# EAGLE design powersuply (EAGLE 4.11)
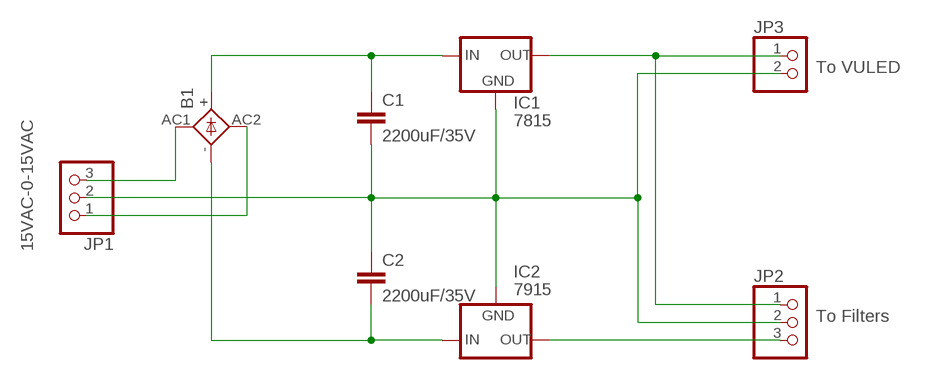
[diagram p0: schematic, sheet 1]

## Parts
B1  1KAB  [1KAB]
C1  2200uF/35V  C7.5/6  [C7.5B6]
C2  2200uF/35V  C7.5/6  [C7.5B6]
IC1  7815  78XXS  [78XXS]
IC2  7915  79XXS  [79XXS]
JP1  PINHD-1X3  [1X03]
JP2  PINHD-1X3  [1X03]
JP3  PINHD-1X2  [1X02]

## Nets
N$1: C1.2 C2.1 IC1.GND IC2.GND JP1.2 JP2.2 JP3.2
N$2: B1.+ C1.1 IC1.IN
N$3: B1.- C2.2 IC2.IN
N$5: B1.AC2 JP1.1
N$6: B1.AC1 JP1.3
N$7: IC2.OUT JP2.3
N$8: IC1.OUT JP2.1 JP3.1

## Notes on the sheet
- To VULED
- 15VAC-0-15VAC
- To Filters

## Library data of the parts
B1 = rectifier:1KAB: RECTIFIER grid 5,08 x 5,08 mm
C1 C2 = capacitor-wima:C: CAPACITOR
IC1 = v-reg:78XXS: VOLTAGE REGULATOR
IC2 = v-reg:79XXS: VOLTAGE REGULATOR
JP1 JP2 = pinhead:PINHD-1X3: PIN HEADER
JP3 = pinhead:PINHD-1X2: PIN HEADER

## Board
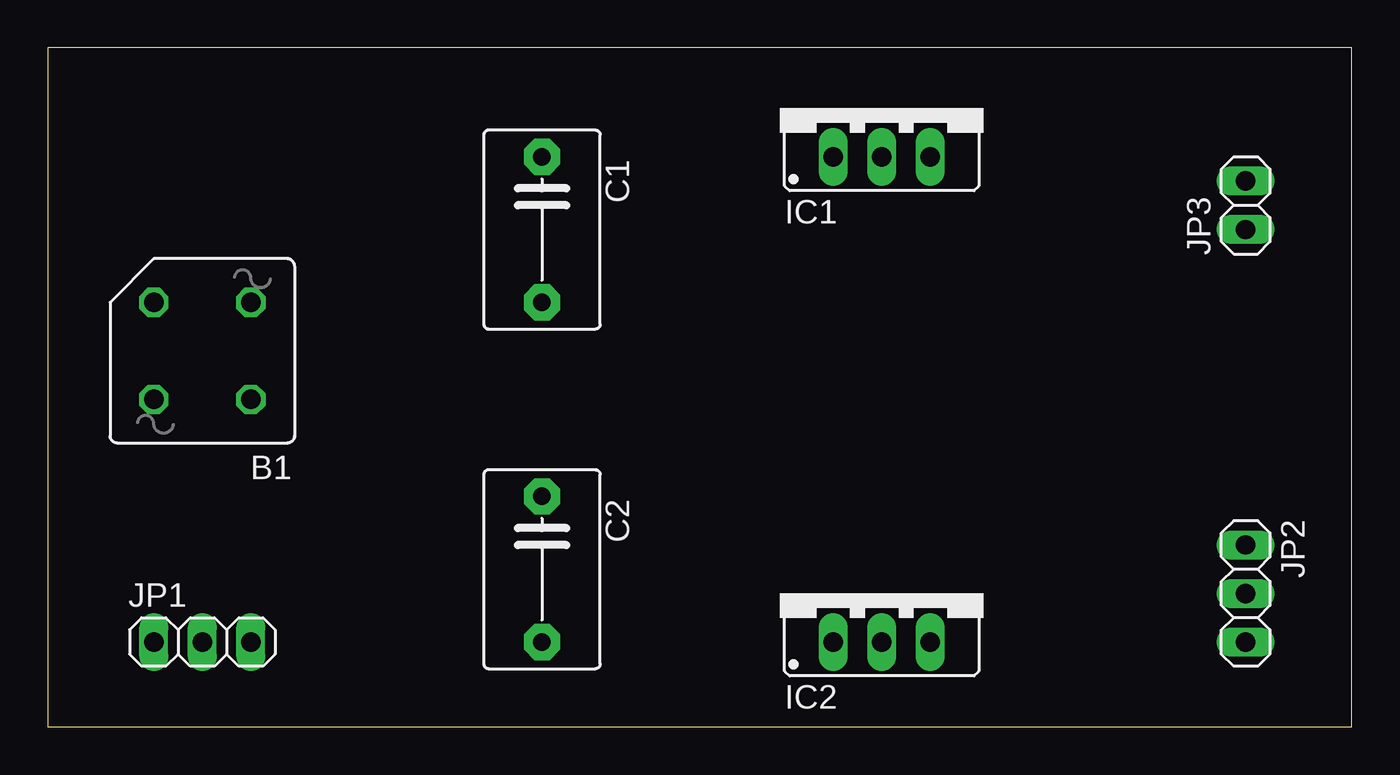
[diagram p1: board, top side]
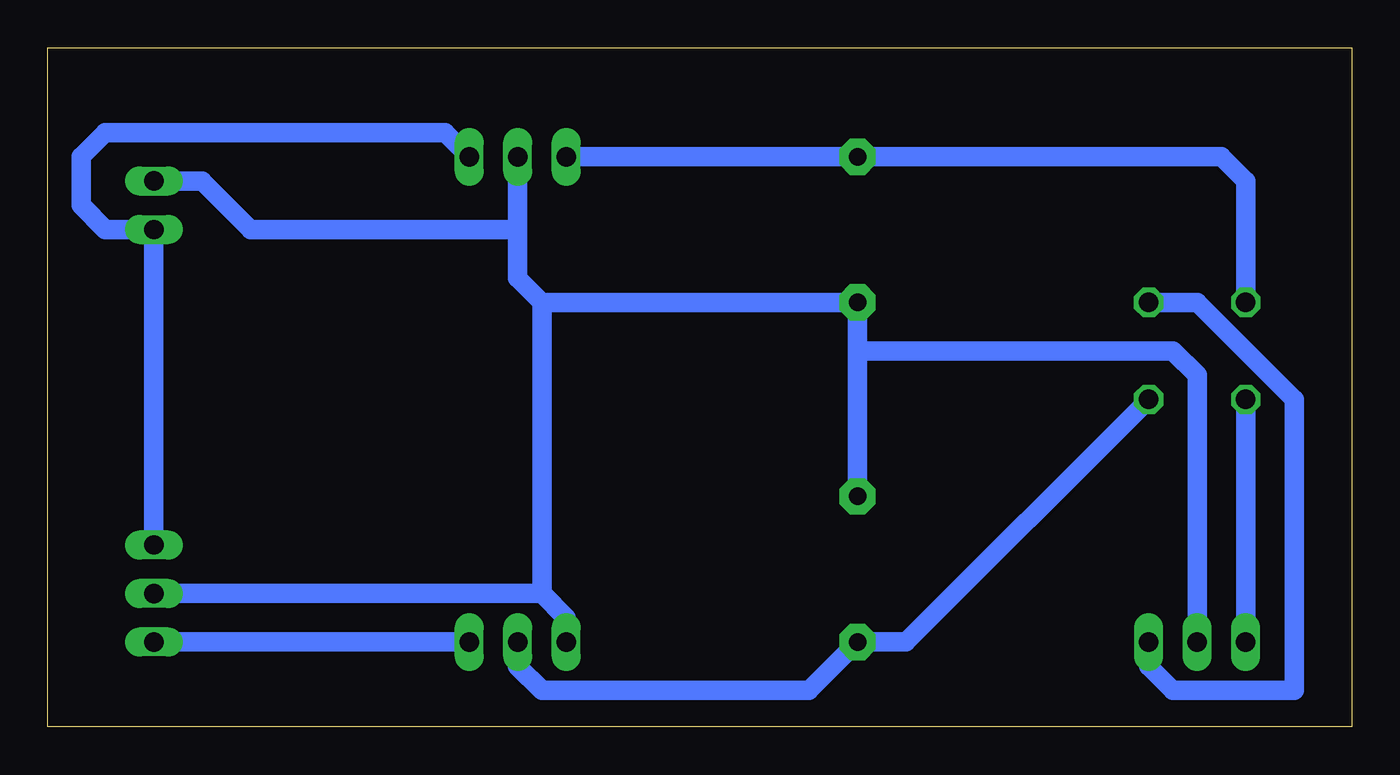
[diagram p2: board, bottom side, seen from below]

Size 68.25 x 35.55 mm. Coordinates in mm from the lower left corner, seen from the top.
Outline: 0,0 68.25,0 68.25,35.55 0,35.55 0,0
Copper layers (1*16): Top 0.035mm / dielectric 1.5mm / Bottom 0.035mm
Design rules "default": minimum track width 10mil, minimum drill 24mil, track to track 8mil, track to pad 8mil, pad to pad 8mil, via to via 8mil, smd to smd 8mil, copper to edge 40mil, drill to drill 8mil, minimum pad ring 10mil, minimum via ring 8mil, stop-mask expansion 4mil, vias tented up to drill 0mil, thermal gap 10mil

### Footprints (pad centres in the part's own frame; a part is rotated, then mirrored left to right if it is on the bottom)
1KAB = drill 1.016 octagon: + 2.54,-2.54; - -2.54,2.54; AC1 -2.54,-2.54; AC2 2.54,2.54
C7.5B6 = drill 0.914 pad 1.905 octagon: 1 -3.81,0; 2 3.81,0
78XXS = drill 1.016 long: GND 0,-2.54; IN -2.54,-2.54; OUT 2.54,-2.54
79XXS = drill 1.016 long: GND -2.54,-2.54; IN 0,-2.54; OUT 2.54,-2.54
1X03 = drill 1.016 long: 1 -2.54,0; 2 0,0; 3 2.54,0
1X02 = drill 1.016 long: 1 -1.27,0; 2 1.27,0

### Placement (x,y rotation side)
B1  8.09,19.68 180 top
C1  25.87,26.03 270 top
C2  25.87,8.25 270 top
IC1  43.65,32.38 0 top
IC2  43.65,6.98 0 top
JP1  8.09,4.44 0 top
JP2  62.7,6.98 270 top
JP3  62.7,27.3 90 top

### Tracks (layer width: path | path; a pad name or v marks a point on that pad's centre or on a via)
N$1
  Bottom 1.016: 42.38,6.98 41.11,5.71 IC2.GND | JP1.2 8.09,18.41 9.36,19.68 25.87,19.68 | 43.65,26.03 43.65,23.49 42.38,22.22 | 42.38,22.22 C1.2 25.87,19.68 | 43.65,26.03 IC1.GND | 43.65,26.03 57.62,26.03 60.16,28.57 JP3.2 | 42.38,6.98 JP2.2 | 25.87,19.68 C2.1 | 42.38,22.22 42.38,6.98
N$2
  Bottom 1.016: B1.+ 5.55,28.57 6.82,29.84 C1.1 IC1.IN
N$3
  Bottom 1.016: IC2.IN 43.65,3.17 42.38,1.9 28.41,1.9 C2.2 23.33,4.44 B1.-
N$5
  Bottom 1.016: JP1.1 B1.AC2
N$6
  Bottom 1.016: B1.AC1 8.09,22.22 3.01,17.14 3.01,1.9 9.36,1.9 10.63,3.17 JP1.3
N$7
  Bottom 1.016: IC2.OUT JP2.3
N$8
  Bottom 1.016: JP2.1 JP3.1 65.24,26.03 66.51,27.3 66.51,29.84 65.24,31.11 47.46,31.11 IC1.OUT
